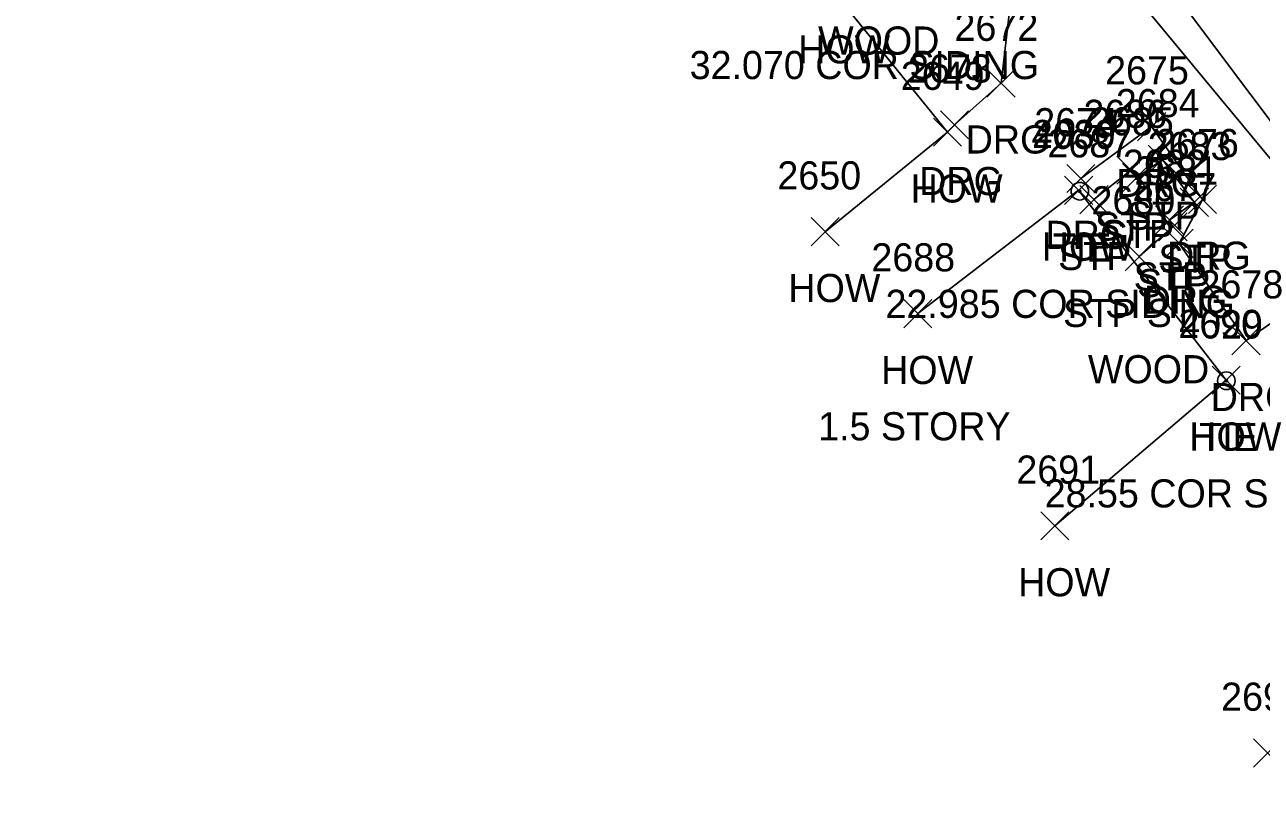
# Model space of a CAD drawing. Extents: x 1634209 to 1639641, y 608564 to 612258.
# Drawn here: x 1639153.3 to 1639241.2, y 611070.4 to 611125 of the extents above; entities that cross this region are included whole.
import ezdxf

# ---------------------------------------------------------------- set-up
doc = ezdxf.new("R2010")
doc.units = 0
for name, color, linetype in [('C_A', 7, 'Continuous'), ('C_C', 7, 'Continuous'), ('C_I', 7, 'Continuous'), ('CBP', 7, 'Continuous'), ('DCP', 7, 'Continuous'), ('L_A', 7, 'Continuous'), ('L_C', 7, 'Continuous'), ('L_I', 7, 'Continuous'), ('L_TIC', 7, 'Continuous'), ('LBC', 7, 'Continuous'), ('LBF', 7, 'Continuous'), ('PET', 7, 'Continuous'), ('R_A', 7, 'Continuous'), ('R_I', 7, 'Continuous'), ('R_TIC', 7, 'Continuous'), ('RDG', 7, 'Continuous')]:
    doc.layers.add(name, color=color, linetype=linetype)

msp = doc.modelspace()

# ---------------------------------------------------------------- linework, layer by layer
at = {"layer": 'CBP'}
for centre, radius in [((1639228.28, 611113.163), 0.625), ((1639228.28, 611113.163), 0.0833), ((1639238.687, 611099.699), 0.625), ((1639238.687, 611099.699), 0.0833)]:
    msp.add_circle(centre, radius, dxfattribs=at)
at = {"layer": 'DCP'}
msp.add_lwpolyline([(1639280.744, 611068.51), (1639160.798, 611213.264)], dxfattribs=at)
at = {"layer": 'L_TIC'}
for points in [[(1639217.875, 611116.361), (1639219.875, 611118.361)], [(1639219.875, 611116.361), (1639217.875, 611118.361)], [(1639233.146, 611114.423), (1639235.146, 611116.423)], [(1639235.146, 611114.423), (1639233.146, 611116.423)], [(1639230.899, 611113.66), (1639232.899, 611115.66)], [(1639232.899, 611113.66), (1639230.899, 611115.66)], [(1639231.313, 611113.125), (1639233.313, 611115.125)], [(1639233.313, 611113.125), (1639231.313, 611115.125)], [(1639227.195, 611112.231), (1639229.195, 611114.231)], [(1639229.195, 611112.231), (1639227.195, 611114.231)], [(1639228.285, 611111.565), (1639230.285, 611113.565)], [(1639230.285, 611111.565), (1639228.285, 611113.565)], [(1639235.412, 611111.374), (1639237.412, 611113.374)], [(1639237.412, 611111.374), (1639235.412, 611113.374)], [(1639233.648, 611110.114), (1639235.648, 611112.114)], [(1639235.648, 611110.114), (1639233.648, 611112.114)], [(1639209.188, 611109.286), (1639211.188, 611111.286)], [(1639211.188, 611109.286), (1639209.188, 611111.286)], [(1639233.896, 611109.636), (1639235.896, 611111.636)], [(1639235.896, 611109.636), (1639233.896, 611111.636)], [(1639231.501, 611107.518), (1639233.501, 611109.518)], [(1639233.501, 611107.518), (1639231.501, 611109.518)], [(1639215.779, 611103.466), (1639217.779, 611105.466)], [(1639217.779, 611103.466), (1639215.779, 611105.466)], [(1639237.675, 611098.737), (1639239.675, 611100.737)], [(1639239.675, 611098.737), (1639237.675, 611100.737)], [(1639225.511, 611088.387), (1639227.511, 611090.387)], [(1639227.511, 611088.387), (1639225.511, 611090.387)], [(1639240.626, 611072.259), (1639242.626, 611074.259)], [(1639242.626, 611072.259), (1639240.626, 611074.259)]]:
    msp.add_lwpolyline(points, dxfattribs=at)
at = {"layer": 'LBC'}
for points in [[(1639182.699, 611140.617), (1639193.271, 611148.998), (1639201.505, 611139.119), (1639205.009, 611141.936), (1639214.503, 611130.111), (1639210.883, 611127.244), (1639218.875, 611117.361), (1639210.188, 611110.286)], [(1639216.779, 611104.466), (1639228.195, 611113.231), (1639238.675, 611099.737), (1639226.511, 611089.387)]]:
    msp.add_lwpolyline(points, dxfattribs=at)
at = {"layer": 'LBF'}
msp.add_lwpolyline([(1639232.501, 611108.518), (1639234.896, 611110.636), (1639234.648, 611111.114), (1639236.412, 611112.374), (1639234.146, 611115.423), (1639232.313, 611114.125), (1639231.899, 611114.66), (1639229.285, 611112.565)], dxfattribs=at)
at = {"layer": 'PET'}
msp.add_lwpolyline([(1639410.825, 610892.364), (1639390.458, 610919.541), (1639371.801, 610946.358), (1639349.879, 610975.696), (1639327.189, 611005.386), (1639302.754, 611038.38), (1639275.028, 611075.512), (1639248.834, 611108.817), (1639223.626, 611142.441), (1639205.296, 611166.276), (1639182.184, 611194.122), (1639165.678, 611212.038), (1639150.219, 611225.989), (1639136.405, 611234.042), (1639135.28, 611232.533), (1639130.918, 611235.275), (1639127.562, 611237.663), (1639124.139, 611238.638)], dxfattribs=at)
at = {"layer": 'R_TIC'}
for points in [[(1639221.685, 611119.842), (1639223.685, 611121.842)], [(1639223.685, 611119.842), (1639221.685, 611121.842)], [(1639218.384, 611116.884), (1639220.384, 611118.884)], [(1639220.384, 611116.884), (1639218.384, 611118.884)], [(1639232.385, 611116.753), (1639234.385, 611118.753)], [(1639234.385, 611116.753), (1639232.385, 611118.753)], [(1639227.352, 611113.064), (1639229.352, 611115.064)], [(1639229.352, 611113.064), (1639227.352, 611115.064)], [(1639235.991, 611111.584), (1639237.991, 611113.584)], [(1639237.991, 611111.584), (1639235.991, 611113.584)], [(1639234.335, 611108.46), (1639236.335, 611110.46)], [(1639236.335, 611108.46), (1639234.335, 611110.46)], [(1639239.09, 611101.549), (1639241.09, 611103.549)], [(1639241.09, 611101.549), (1639239.09, 611103.549)]]:
    msp.add_lwpolyline(points, dxfattribs=at)
at = {"layer": 'RDG'}
for points in [[(1639224.755, 611138.679), (1639222.685, 611120.842), (1639219.384, 611117.884)], [(1639228.352, 611114.064), (1639233.385, 611117.753), (1639236.991, 611112.584), (1639235.335, 611109.46), (1639240.09, 611102.549), (1639248.401, 611108.361)]]:
    msp.add_lwpolyline(points, dxfattribs=at)

# ---------------------------------------------------------------- texts
at = {"layer": 'C_A'}
for p in [(1639226.359, 611108.163), (1639236.766, 611094.699)]:
    msp.add_text('TIE', height=2, dxfattribs=at).set_placement(p)
at = {"layer": 'C_C'}
for s, p in [('32.070 COR SIDING', (1639200.564, 611121.126)), ('22.985 COR SIDING', (1639214.477, 611104.163)), ('28.55 COR SIDING', (1639225.782, 611090.699))]:
    msp.add_text(s, height=2, dxfattribs=at).set_placement(p)
at = {"layer": 'C_I'}
for s, p in [('4030', (1639224.855, 611116.163)), ('4029', (1639235.341, 611102.699))]:
    msp.add_text(s, height=2, dxfattribs=at).set_placement(p)
at = {"layer": 'L_A'}
for s, p in [('HOW', (1639208.269, 611122.244)), ('HOW', (1639216.261, 611112.361)), ('STP', (1639231.603, 611110.423)), ('STP', (1639229.356, 611109.66)), ('STP', (1639229.77, 611109.125)), ('HOW', (1639225.58, 611108.231)), ('STP', (1639226.742, 611107.565)), ('STP', (1639233.869, 611107.374)), ('STP', (1639232.105, 611106.114)), ('STP', (1639232.352, 611105.636)), ('HOW', (1639207.574, 611105.286)), ('STP ST', (1639227.092, 611103.518)), ('HOW', (1639214.165, 611099.466)), ('HOW', (1639236.061, 611094.737)), ('HOW', (1639223.897, 611084.387))]:
    msp.add_text(s, height=2, dxfattribs=at).set_placement(p)
at = {"layer": 'L_C'}
for s, p in [('WOOD', (1639209.69, 611122.867)), ('WOOD', (1639228.856, 611099.518)), ('1.5 STORY', (1639209.692, 611095.466))]:
    msp.add_text(s, height=2, dxfattribs=at).set_placement(p)
at = {"layer": 'L_I'}
for s, p in [('2649', (1639215.56, 611120.361)), ('2684', (1639230.839, 611118.423)), ('2686', (1639228.537, 611117.66)), ('2685', (1639229.006, 611117.125)), ('2689', (1639224.88, 611116.231)), ('2687', (1639225.978, 611115.565)), ('2683', (1639233.105, 611115.374)), ('2682', (1639231.341, 611114.114)), ('2681', (1639232.156, 611113.636)), ('2650', (1639206.794, 611113.286)), ('2680', (1639229.108, 611111.518)), ('2688', (1639213.472, 611107.466)), ('2690', (1639235.282, 611102.737)), ('2691', (1639223.771, 611092.387)), ('2692', (1639238.319, 611076.259))]:
    msp.add_text(s, height=2, dxfattribs=at).set_placement(p)
at = {"layer": 'R_A'}
for p in [(1639220.173, 611115.842), (1639216.872, 611112.884), (1639230.873, 611112.753), (1639225.84, 611109.064), (1639234.479, 611107.584), (1639232.823, 611104.46), (1639237.578, 611097.549)]:
    msp.add_text('DRG', height=2, dxfattribs=at).set_placement(p)
at = {"layer": 'R_I'}
for s, p in [('2672', (1639219.378, 611123.842)), ('2673', (1639216.077, 611120.884)), ('2675', (1639230.078, 611120.753)), ('2674', (1639225.045, 611117.064)), ('2676', (1639233.629, 611115.584)), ('2677', (1639232.028, 611112.46)), ('2678', (1639236.783, 611105.549))]:
    msp.add_text(s, height=2, dxfattribs=at).set_placement(p)

doc.saveas('drawing.dxf')
